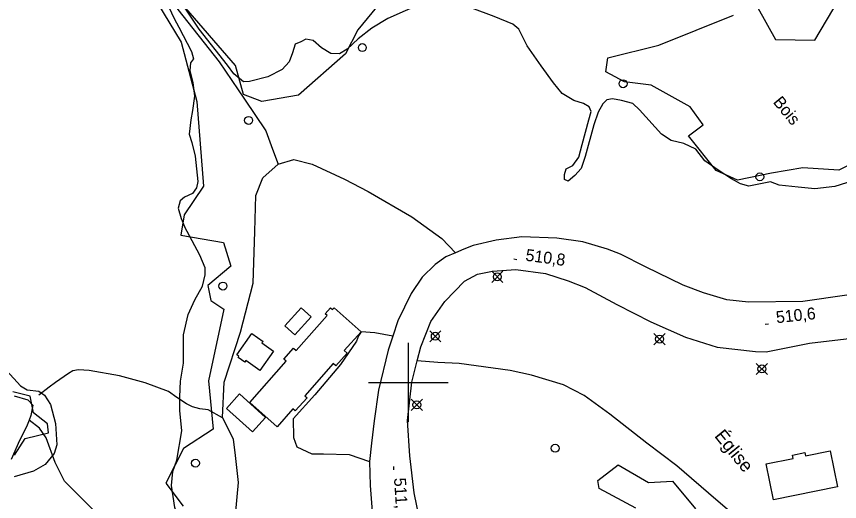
# Model space of a CAD drawing. Extents: x 347312 to 350503, y 6073086 to 6076432.
# Drawn here: x 348201.2 to 348408.7, y 6075570 to 6075692.2 of the extents above; entities that cross this region are included whole.
import ezdxf

# ---------------------------------------------------------------- set-up
doc = ezdxf.new("R2010")
doc.units = 0
for name, color, linetype in [('Level 1', 7, 'Continuous'), ('Level 19', 7, 'Continuous'), ('Level 2', 7, 'Continuous'), ('Level 21', 7, 'Continuous'), ('Level 22', 7, 'Continuous'), ('Level 3', 7, 'Continuous'), ('Level 31', 7, 'Continuous'), ('Level 36', 7, 'Continuous'), ('Level 4', 7, 'Continuous'), ('Level 44', 7, 'Continuous'), ('Level 61', 7, 'Continuous')]:
    doc.layers.add(name, color=color, linetype=linetype)

msp = doc.modelspace()

# ---------------------------------------------------------------- linework, layer by layer
at = {"layer": 'Level 1'}
for points in [[(348239.27, 6075697.49), (348239, 6075696), (348240.97, 6075691.65), (348242.16, 6075689.52), (348245.37, 6075683.41), (348245.86, 6075681.52), (348245.09, 6075680.49), (348244.91, 6075678.59), (348245.67, 6075675.58), (348246.09, 6075672.15), (348245.6, 6075668.52), (348245.15, 6075666.14), (348244.74, 6075662.57), (348245.44, 6075660.44), (348246.3, 6075656.98), (348246.97, 6075650.66), (348246.59, 6075649), (348245.57, 6075647.63), (348243.63, 6075646.71), (348242.5, 6075645.78), (348242.03, 6075643.91), (348242.74, 6075641.27), (348243.6, 6075639.28)], [(348303.6, 6075695.54), (348294.85, 6075691.72), (348290.83, 6075689.23), (348287.38, 6075686.53), (348284.62, 6075684), (348282.64, 6075682.78), (348280.5, 6075682.91), (348278.11, 6075684.31), (348276.05, 6075686.12), (348274.15, 6075686.45), (348272.91, 6075685.83), (348271.51, 6075685.22), (348270.79, 6075683.01), (348269.98, 6075680.73), (348268.17, 6075678.84), (348264.58, 6075676.97), (348260.01, 6075675.78), (348258.45, 6075675.7), (348256.04, 6075677.77), (348254.39, 6075679.91), (348247.3, 6075689.04), (348243.08, 6075695.34)], [(348381.42, 6075651.26), (348378.06, 6075653.5), (348374.71, 6075655.87), (348372.45, 6075658.74), (348369.46, 6075660.2), (348366.25, 6075660.94), (348363.8, 6075662.57), (348358.27, 6075668.69), (348356.55, 6075670.25), (348353.72, 6075671.04), (348351.46, 6075671.47), (348350.02, 6075671.24), (348349.03, 6075670.15), (348347.87, 6075668.12), (348346.75, 6075664.91), (348344.59, 6075656.94), (348343.57, 6075653.94), (348341.98, 6075652.1), (348340.29, 6075650.71), (348339.37, 6075651.17), (348339.33, 6075652.35), (348339.76, 6075653.78), (348341.48, 6075654.65), (348343.01, 6075656.72), (348343.83, 6075659.95), (348345.53, 6075666.2), (348346.1, 6075668.29), (348345.54, 6075669.45), (348344.13, 6075670.31), (348341.67, 6075670.99), (348338.79, 6075672.8), (348336.58, 6075675.44), (348333.49, 6075679.78), (348329.95, 6075684.83), (348327.81, 6075689.01), (348326.37, 6075690.25), (348321.64, 6075692.16), (348316.04, 6075694.3)], [(348416.55, 6075652.18), (348407.51, 6075649.4), (348402.48, 6075648.76), (348398.22, 6075649.19), (348393.46, 6075649.66), (348391.29, 6075650.55), (348385.85, 6075649.41), (348383.69, 6075650.02), (348381.42, 6075651.26)], [(348244.2, 6075560.31), (348242.95, 6075563.59), (348241.18, 6075568.47), (348240.3, 6075574.08), (348240.62, 6075577.58), (348241.63, 6075580.43), (348242.92, 6075587.82), (348242.44, 6075592.94), (348242.39, 6075596.41), (348242.61, 6075600.36), (348243.33, 6075604.86), (348243.34, 6075611.99), (348244.48, 6075617.11), (348246.16, 6075620.78), (348248.13, 6075624.28), (348248.84, 6075627.15), (348248.78, 6075628.85), (348247.45, 6075632.07), (348243.6, 6075639.28)]]:
    msp.add_lwpolyline(points, dxfattribs=at)
at = {"layer": 'Level 19'}
msp.add_lwpolyline([(348296.11, 6075611.66), (348291.57, 6075612.46), (348288.08, 6075612.78), (348287.42, 6075611.76), (348286.92, 6075610.37), (348282.93, 6075604.52), (348276.4, 6075596.85), (348271, 6075590.8), (348271.09, 6075586.17), (348271.89, 6075583.77), (348275.65, 6075582.03), (348278.64, 6075582.04), (348285.13, 6075581.82), (348290.21, 6075580.13)], dxfattribs=at)
at = {"layer": 'Level 2'}
msp.add_lwpolyline([(348198.84, 6075602.94), (348202.27, 6075599.15), (348203.95, 6075598.11), (348206.9, 6075597.83), (348208.29, 6075596.81), (348209.85, 6075594.45), (348211.11, 6075589.69), (348211.42, 6075584.28), (348210.77, 6075582.13), (348208.5, 6075579.33), (348205.52, 6075577.69), (348200.63, 6075576.24)], dxfattribs=at)
at = {"layer": 'Level 21'}
for points in [[(348410.53, 6075621.99), (348399.46, 6075620.38), (348385.7, 6075620.2), (348380.31, 6075620.81), (348374.36, 6075622.55), (348369.3, 6075624.48), (348359.81, 6075629.12), (348353.43, 6075632.36), (348350.23, 6075633.6), (348343.97, 6075635.44), (348337.45, 6075636.32), (348328.64, 6075636.72), (348322.17, 6075635.83), (348316.38, 6075634.48), (348313.97, 6075633.59), (348311.87, 6075632.69), (348309.48, 6075631.67), (348306.8, 6075629.74), (348303.51, 6075626.56), (348300.75, 6075622.4), (348297.39, 6075615.5), (348296.11, 6075611.66), (348294.94, 6075608.15), (348292.47, 6075598.02), (348291.37, 6075590.3), (348290.68, 6075584.71), (348290.21, 6075580.13), (348290.41, 6075574.01), (348290.96, 6075566.39)], [(348303.47, 6075562.4), (348301.44, 6075572.16), (348300.36, 6075581.51), (348299.8, 6075590.41), (348300.88, 6075600.05), (348302.26, 6075605.41), (348303.19, 6075609.01), (348305.64, 6075615.38), (348309.18, 6075620.42), (348314.17, 6075625.53), (348317.45, 6075627.28), (348321.2, 6075628), (348327.11, 6075628.49), (348334.59, 6075627.43), (348340.32, 6075625.6), (348344.58, 6075623.9), (348352.55, 6075619.65), (348361.11, 6075615.3), (348369.85, 6075611.39), (348377.86, 6075608.9), (348387.47, 6075607.81), (348390.17, 6075607.73), (348401.12, 6075609.93), (348416.09, 6075611.63)]]:
    msp.add_lwpolyline(points, dxfattribs=at)
at = {"layer": 'Level 22'}
for points in [[(348205.11, 6075782.99), (348211.46, 6075780.11), (348213.17, 6075776.88), (348214.84, 6075768.59), (348218.27, 6075763.35), (348223.76, 6075758.36), (348228.85, 6075753.32), (348230.52, 6075750.66), (348234.19, 6075743.03), (348235.03, 6075735.7), (348235.09, 6075729.98), (348235.62, 6075714.19), (348237.89, 6075702.03), (348241.93, 6075693.97), (348252.34, 6075680.77), (348258.72, 6075671.4), (348264.06, 6075663.41), (348265.8, 6075658.8), (348267.17, 6075655.01)], [(348256.44, 6075566.66), (348257.21, 6075574.77), (348256.46, 6075581.63), (348255.95, 6075585.68), (348253.19, 6075591.17), (348253.62, 6075600.06), (348257.68, 6075612.69), (348260.87, 6075625), (348261.35, 6075638.01), (348261.54, 6075647.13), (348263.34, 6075651.56), (348267.17, 6075655.01), (348271.16, 6075656.18), (348275.79, 6075655.01), (348283.89, 6075651.21), (348289.84, 6075648.14), (348300.91, 6075641.75), (348308.48, 6075636.28), (348311.87, 6075632.69)], [(348444.57, 6075509.86), (348441.3, 6075513.61), (348436.27, 6075518.58), (348431.63, 6075523.44), (348422.96, 6075532.61), (348413.95, 6075542.55), (348403.54, 6075554.09), (348398.41, 6075558.99), (348394.05, 6075561.98), (348387.3, 6075563.87), (348381.53, 6075567.1), (348377.47, 6075570.55), (348367.64, 6075579.03), (348360.1, 6075584.67), (348350.75, 6075592.04), (348344.34, 6075596.68), (348339.07, 6075599.42), (348331.06, 6075601.83), (348325.65, 6075603.02), (348312.79, 6075604.77), (348307.45, 6075605.05), (348302.26, 6075605.41)], [(348253.21, 6075591.13), (348249.6, 6075593.14), (348247.45, 6075593.38), (348245.57, 6075593.84), (348244.12, 6075594.59), (348241.7, 6075596.24), (348239.59, 6075597.7), (348233.65, 6075599.89), (348227.22, 6075601.66), (348219.57, 6075603.02), (348216.92, 6075603.14), (348215.46, 6075602.9), (348214.33, 6075602.27), (348211.09, 6075600.03), (348209.5, 6075598.78), (348206.85, 6075596.81)]]:
    msp.add_lwpolyline(points, dxfattribs=at)
at = {"layer": 'Level 3'}
for p, q in [((348326.56, 6075631.11), (348327.35, 6075631.01)), ((348389.94, 6075614.65), (348390.74, 6075614.73)), ((348296.25, 6075578.79), (348296.29, 6075577.99))]:
    msp.add_line(p, q, dxfattribs=at)
at = {"layer": 'Level 31'}
for points in [[(348266.95, 6075588.86), (348260.06, 6075594.98), (348269.25, 6075605.34), (348268.63, 6075605.9), (348271.05, 6075608.63), (348271.73, 6075608.02), (348279.57, 6075616.86), (348279.06, 6075617.31), (348280.4, 6075618.82), (348280.92, 6075618.36), (348281.31, 6075618.79), (348288.08, 6075612.78), (348283.85, 6075608.01), (348284.6, 6075607.35), (348281.77, 6075604.16), (348281.08, 6075604.77), (348273.9, 6075596.67), (348274.48, 6075596.16), (348271.52, 6075592.82), (348270.92, 6075593.35), (348266.95, 6075588.86)], [(348275.48, 6075616.53), (348271.38, 6075612.01), (348268.89, 6075614.27), (348272.99, 6075618.79), (348275.48, 6075616.53)], [(348262.61, 6075603.02), (348259.05, 6075605.51), (348258.78, 6075605.13), (348257.08, 6075606.32), (348257.3, 6075606.62), (348256.79, 6075606.97), (348260.54, 6075612.33), (348263.38, 6075610.35), (348263.12, 6075609.96), (348266.03, 6075607.92), (348262.61, 6075603.02)], [(348260.72, 6075587.53), (348254.17, 6075593.44), (348257.47, 6075597.1), (348264.02, 6075591.19), (348260.72, 6075587.53)], [(348408.15, 6075573.73), (348392.02, 6075570.43), (348390.17, 6075579.48), (348397.02, 6075580.88), (348396.84, 6075581.71), (348399.96, 6075582.35), (348400.13, 6075581.49), (348406.3, 6075582.75), (348408.15, 6075573.73)]]:
    msp.add_lwpolyline(points, dxfattribs=at)
at = {"layer": 'Level 36'}
for p, q in [((348321.02, 6075625.21), (348323.84, 6075628.03)), ((348321.02, 6075628.03), (348323.84, 6075625.21)), ((348305.39, 6075610.22), (348308.21, 6075613.04)), ((348305.39, 6075613.04), (348308.21, 6075610.22)), ((348361.91, 6075609.51), (348364.73, 6075612.33)), ((348361.91, 6075612.33), (348364.73, 6075609.51)), ((348387.69, 6075601.99), (348390.51, 6075604.81)), ((348387.69, 6075604.81), (348390.51, 6075601.99)), ((348300.74, 6075592.96), (348303.56, 6075595.78)), ((348300.74, 6075595.78), (348303.56, 6075592.96))]:
    msp.add_line(p, q, dxfattribs=at)
for centre in [(348288.41, 6075684.35), (348354.13, 6075675.25), (348259.74, 6075666.01), (348388.58, 6075651.8), (348322.43, 6075626.62), (348253.27, 6075624.29), (348306.8, 6075611.63), (348363.32, 6075610.92), (348389.1, 6075603.4), (348302.15, 6075594.37), (348337, 6075583.42), (348246.36, 6075579.67)]:
    msp.add_circle(centre, 1, dxfattribs=at)
at = {"layer": 'Level 4'}
for points in [[(348200.63, 6075596.65), (348204.15, 6075595.64), (348205.35, 6075594.32), (348204.87, 6075591.7), (348204.43, 6075590.52), (348203.8, 6075588.8), (348201.99, 6075585.34), (348199.92, 6075580.59)], [(348240.78, 6075550.44), (348236.01, 6075552.92), (348232.19, 6075554.1), (348230.72, 6075555.5), (348228.37, 6075558.79), (348225.82, 6075562.14), (348222.41, 6075566.06), (348217.47, 6075571.02), (348213.35, 6075575.17), (348211.01, 6075579.82), (348208.73, 6075586.09), (348207.03, 6075588.51), (348204.43, 6075590.52)]]:
    msp.add_lwpolyline(points, dxfattribs=at)
at = {"layer": 'Level 44'}
for points in [[(348296.25, 6075699.86), (348287.27, 6075688.81), (348284.17, 6075682.8), (348272.3, 6075672.35), (348263.07, 6075670.82), (348258.49, 6075672.55), (348256.48, 6075679.84), (348242.83, 6075695.56)], [(348419.74, 6075698.58), (348428.98, 6075674.25), (348432.24, 6075665.81), (348428.4, 6075663.38), (348417.82, 6075666.14), (348414.04, 6075661.65), (348412.82, 6075655.7), (348408.51, 6075653.47), (348399.46, 6075654.05), (348391.55, 6075652.72), (348382.94, 6075650.97), (348377.59, 6075653.42), (348370.63, 6075662.16), (348374.33, 6075664.94), (348371.06, 6075669.41), (348361.24, 6075674.89), (348354.52, 6075675.75), (348349.75, 6075678.24), (348350.25, 6075681.79), (348363.09, 6075684.97), (348381.93, 6075692.51)], [(348236.77, 6075695.57), (348242.79, 6075685.73), (348246.72, 6075670.76), (348248.38, 6075649.43), (348243.53, 6075642.22), (348242.66, 6075637.07), (348253.42, 6075635.26), (348255.25, 6075629.26), (348249.44, 6075624.4), (348250.22, 6075620.67)], [(348388.06, 6075694.34), (348392.57, 6075686.39), (348402.48, 6075686.23), (348408.54, 6075696.65)], [(348250.22, 6075620.67), (348253.47, 6075618.47), (348249.61, 6075600.42), (348250.82, 6075588.27), (348243.38, 6075583.38), (348238.9, 6075574.67), (348243.27, 6075568.87)], [(348200.79, 6075581.67), (348203.48, 6075585.85), (348209.35, 6075587.28), (348209.08, 6075589.6), (348205.57, 6075592.38), (348204.66, 6075596.57), (348200.33, 6075597.62)], [(348357.3, 6075568.36), (348348.1, 6075573.3), (348347.79, 6075575.3), (348352.92, 6075579.25), (348360.53, 6075574.78), (348366.55, 6075575.13), (348372.37, 6075568.13)]]:
    msp.add_lwpolyline(points, dxfattribs=at)
at = {"layer": 'Level 61'}
for p, q in [((348300, 6075610), (348300, 6075590)), ((348290, 6075600), (348310, 6075600))]:
    msp.add_line(p, q, dxfattribs=at)

# ---------------------------------------------------------------- texts
at = {"layer": 'Level 3'}
for s, rotation, p in [('510,8', 352.2919, (348329.41, 6075630.69)), ('510,6', 6.0614, (348392.81, 6075614.92)), ('511,0', 273.5332, (348296.39, 6075575.91))]:
    msp.add_text(s, height=3, rotation=rotation, dxfattribs=at).set_placement(p)
at = {"layer": 'Level 31'}
msp.add_text('Église', height=3.33, rotation=309.1656, dxfattribs=at).set_placement((348376.99, 6075586.46))
at = {"layer": 'Level 44'}
msp.add_text('Bois', height=3, rotation=309.568, dxfattribs=at).set_placement((348391.76, 6075670.56))

doc.saveas('drawing.dxf')
